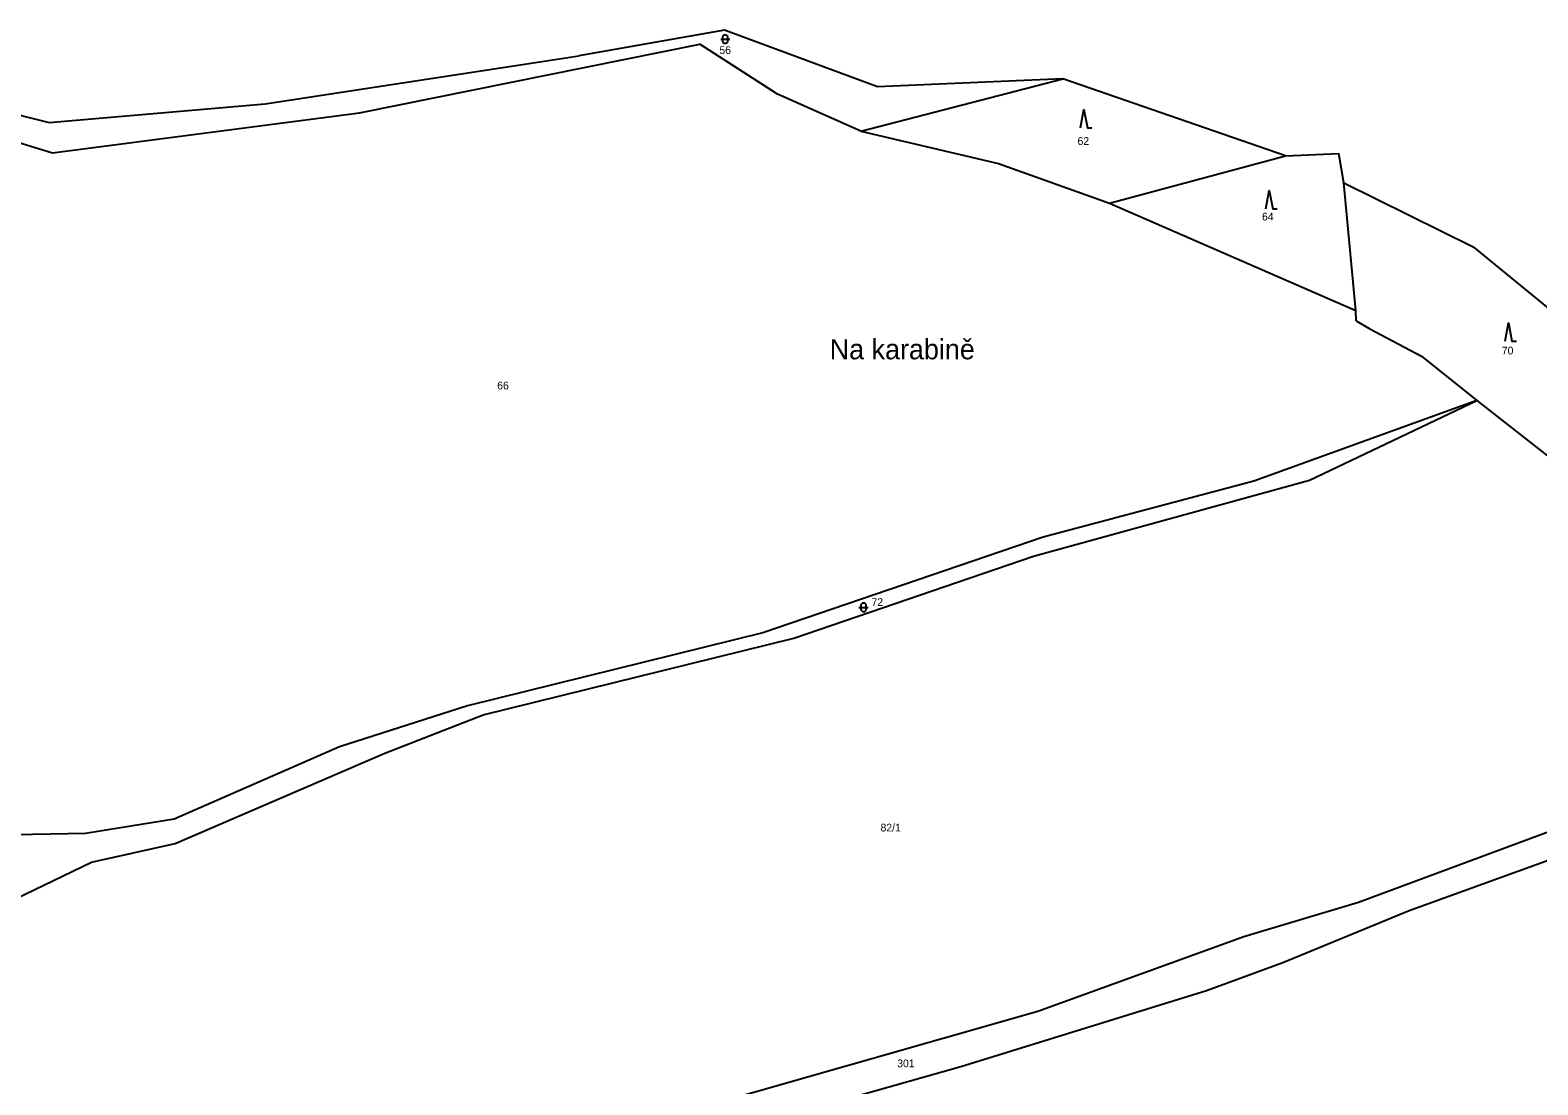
# Model space of a CAD drawing. Extents: x -779723 to -777378, y -1011169 to -1009297.
# Drawn here: x -778986.4 to -778656.8, y -1010119.6 to -1009889 of the extents above; entities that cross this region are included whole.
import ezdxf

# ---------------------------------------------------------------- set-up
doc = ezdxf.new("R2010")
doc.units = 0
for name, color, linetype in [('Default', 7, 'Continuous'), ('KN_HRANICE', 7, 'Continuous'), ('KN_KULTURY', 7, 'Continuous'), ('KN_PARCELY', 7, 'Continuous')]:
    doc.layers.add(name, color=color, linetype=linetype)

# ---------------------------------------------------------------- blocks, each defined once
blk = doc.blocks.new('308')
at = {"layer": 'Default'}
blk.add_lwpolyline([(-0.75, 0), (0, 4), (0.75, 0), (1.75, 0)], dxfattribs=at)
blk = doc.blocks.new('316')
at = {"layer": 'Default'}
for points in [[(-1, 1), (0.27, 1), (1, 1)], [(-0.5, 1.5), (-0.4, 1.79), (-0.15, 1.97), (0.16, 1.97), (0.41, 1.79), (0.51, 1.5), (0.51, 0.5), (0.41, 0.21), (0.16, 0.03), (-0.15, 0.03), (-0.4, 0.21), (-0.5, 0.5), (-0.5, 1.5)]]:
    blk.add_lwpolyline(points, dxfattribs=at)

msp = doc.modelspace()

# ---------------------------------------------------------------- linework, layer by layer
at = {"layer": 'KN_HRANICE'}
for p, q in [((-778834.56, -1009889.02), (-778866.47, -1009894.62)), ((-778801.13, -1009901.44), (-778834.56, -1009889.02)), ((-778914.43, -1009907.12), (-778840, -1009892.06)), ((-778874.97, -1009895.93), (-778866.47, -1009894.62)), ((-778823.02, -1009903.04), (-778840, -1009892.06)), ((-778935.03, -1009905.15), (-778874.97, -1009895.93)), ((-778804.81, -1009911.11), (-778760.64, -1009899.67)), ((-778760.64, -1009899.67), (-778801.13, -1009901.44)), ((-778711.94, -1009916.46), (-778760.64, -1009899.67)), ((-778804.81, -1009911.11), (-778823.02, -1009903.04)), ((-778995.28, -1009905.9), (-778982.29, -1009909.24)), ((-778982.29, -1009909.24), (-778935.03, -1009905.15)), ((-778981.54, -1009915.82), (-778914.43, -1009907.12)), ((-778995.73, -1009911.49), (-778981.54, -1009915.82)), ((-778804.81, -1009911.11), (-778774.65, -1009918.18)), ((-778750.38, -1009926.85), (-778711.94, -1009916.46)), ((-778711.94, -1009916.46), (-778700.3, -1009915.96)), ((-778699.18, -1009922.39), (-778700.3, -1009915.96)), ((-778774.65, -1009918.18), (-778750.38, -1009926.85)), ((-778699.18, -1009922.39), (-778670.88, -1009936.37)), ((-778696.54, -1009950.3), (-778699.18, -1009922.39)), ((-778750.38, -1009926.85), (-778696.54, -1009950.3)), ((-778670.88, -1009936.37), (-778642.47, -1009959.73)), ((-778696.47, -1009952.58), (-778696.54, -1009950.3)), ((-778696.47, -1009952.58), (-778693.5, -1009954.31)), ((-778693.5, -1009954.31), (-778682.19, -1009960.32)), ((-778682.19, -1009960.32), (-778670.06, -1009969.95)), ((-778670.06, -1009969.95), (-778718.88, -1009987.64)), ((-778706.66, -1009987.42), (-778670.06, -1009969.95)), ((-778670.06, -1009969.95), (-778648.43, -1009986.95)), ((-778767.02, -1010004.01), (-778706.66, -1009987.42)), ((-778718.88, -1009987.64), (-778764.89, -1009999.85)), ((-778764.89, -1009999.85), (-778826.21, -1010020.79)), ((-778819.45, -1010021.97), (-778767.02, -1010004.01)), ((-778826.21, -1010020.79), (-778890.8, -1010036.76)), ((-778887.38, -1010038.7), (-778819.45, -1010021.97)), ((-778890.8, -1010036.76), (-778918.78, -1010045.67)), ((-778908.85, -1010047.11), (-778887.38, -1010038.7)), ((-778918.78, -1010045.67), (-778954.93, -1010061.53)), ((-778954.68, -1010066.8), (-778908.85, -1010047.11)), ((-778695.97, -1010079.62), (-778608.15, -1010047.05)), ((-778684.92, -1010081.46), (-778622.94, -1010059.11)), ((-778954.93, -1010061.53), (-778974.33, -1010064.63)), ((-778974.33, -1010064.63), (-778993.67, -1010065.04)), ((-778973, -1010070.94), (-778954.68, -1010066.8)), ((-778994.71, -1010081.37), (-778973, -1010070.94)), ((-778721.06, -1010087.16), (-778695.97, -1010079.62)), ((-778712.5, -1010092.84), (-778684.92, -1010081.46)), ((-778766.08, -1010103.5), (-778721.06, -1010087.16)), ((-778729.23, -1010099), (-778712.5, -1010092.84)), ((-778782.95, -1010115.6), (-778729.23, -1010099)), ((-778869.36, -1010132.88), (-778766.08, -1010103.5)), ((-778810.44, -1010123.41), (-778782.95, -1010115.6))]:
    msp.add_line(p, q, dxfattribs=at)

# ---------------------------------------------------------------- block references
at = {"layer": 'KN_KULTURY'}
for name, p in [('316', (-778834.43, -1009891.99)), ('308', (-778756, -1009910.4)), ('308', (-778715.47, -1009928.08)), ('308', (-778663.16, -1009957.01)), ('316', (-778804.2, -1010016.21))]:
    msp.add_blockref(name, p, dxfattribs=at)

# ---------------------------------------------------------------- texts
at = {"layer": 'KN_PARCELY'}
for s, height, p in [('56', 1.7, (-778835.7, -1009894.24)), ('62', 1.7, (-778757.4, -1009914.12)), ('64', 1.7, (-778717.06, -1009930.63)), ('Na karabině', 4.4, (-778811.59, -1009960.98)), ('70', 1.7, (-778664.63, -1009959.92)), ('66', 1.7, (-778884.29, -1009967.56)), ('72', 1.7, (-778802.45, -1010014.91)), ('82/1', 1.7, (-778800.47, -1010064.2)), ('301', 1.7, (-778796.82, -1010115.75))]:
    msp.add_text(s, height=height, dxfattribs=at).set_placement(p)

doc.saveas('drawing.dxf')
